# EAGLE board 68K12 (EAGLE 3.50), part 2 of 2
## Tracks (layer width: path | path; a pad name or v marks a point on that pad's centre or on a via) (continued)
D6  (via drill 0.61 pad 1.02) (continued)
  Top 0.254: 123.42,15.7 123.42,29.16 122.4,30.18 122.4,31.57 123.42,32.59 123.42,33.48 v123.42,46.43 122.4,47.45 122.4,49.23 123.42,50.24 123.42,51.26 123.42,52.65 122.66,53.42 122.66,65.61 122.4,65.86 122.4,67.26 122.91,67.77 122.91,68.53 123.42,69.04 | v51.28,90.5 51.28,90.88 33.25,90.88 33.25,69.29 36.55,65.99 36.55,60.27 34.77,58.5 34.77,10.62 v35.79,10.62 | v81.51,55.45 80.49,56.46 80.49,65.48 80.75,65.74 80.75,69.55 78.71,71.58 77.95,71.58 76.94,72.59 v76.94,76.4 75.29,78.05 v75.29,78.82 | v54.84,90.5 59.92,85.42 59.92,80.47
  Bottom 0.254: 53.57,9.35 51.03,9.35 49.76,8.08 42.14,8.08 42.14,9.86 41.38,10.62 v35.79,10.62 | v76.94,76.4 79.48,76.4 80.49,75.39 82.78,75.39 | 59.92,80.47 59.92,78.18 74.65,78.18 v75.29,78.82 | v51.28,90.5 v54.84,90.5 | v123.42,46.43 103.86,46.43 103.1,47.19 103.1,48.08 102.46,48.72 101.32,48.72 100.69,48.08 100.69,46.81 100.05,46.18 96.24,46.18 95.48,46.94 95.48,49.23 93.07,49.23 91.8,50.5 85.95,50.5 81.51,54.94 v81.51,55.45
D7  (via drill 0.61 pad 1.02)
  Top 0.254: 125.96,15.7 v125.96,20.52 125.96,28.4 124.94,29.41 124.94,31.57 125.96,32.59 125.96,33.48 125.96,47.19 124.94,48.21 124.94,49.48 125.96,50.5 125.96,51.26 125.96,64.72 124.94,65.74 124.94,67.01 125.45,67.51 125.45,68.53 125.96,69.04 | v62.46,89.23 62.46,80.47 | v131.29,70.56 131.04,70.82 131.04,82.25 130.02,83.26 130.02,86.06 129.77,86.31 v129.77,89.1 | v57.63,11.89 57.63,9.09 56.62,8.08 55.09,8.08 53.82,6.81 53.57,6.81
  Bottom 0.254: 62.46,80.47 63.86,79.07 73.51,79.07 74.52,80.09 76.05,80.09 77.06,79.07 84.18,79.07 85.32,77.93 | v131.29,70.56 127.48,70.56 125.96,69.04 | v57.63,11.89 61.32,11.89 62.59,13.16 65.25,13.16 65.25,15.19 68.3,18.24 69.19,18.24 69.95,17.48 71.6,17.48 72.11,17.98 88.75,17.98 92.68,21.92 104.88,21.92 106.27,20.52 v125.96,20.52 | 51.03,6.81 53.57,6.81 | v62.46,89.23 71.48,89.23 72.11,88.6 103.1,88.6 104.11,89.61 115.8,89.61 116.81,90.63 122.66,90.63 123.93,89.36 129.51,89.36 v129.77,89.1
DX0
  Bottom 0.305: 43.41,27.13 40.87,29.67 40.87,29.92 39.47,31.32 39.47,33.6 38.33,34.75 34.52,34.75 33.25,33.48 21.82,33.48 20.55,34.75 17.37,34.75 16.1,36.02 15.47,36.02 14.83,36.02 13.56,37.29 6.58,37.29 5.31,38.56
DX1
  Bottom 0.305: 5.31,36.02 6.58,34.75 13.56,34.75 14.83,33.48 15.47,33.48 16.1,33.48 17.37,32.21 20.55,32.21 21.82,30.94 33.88,30.94 35.15,32.21 38.33,32.21 38.33,31.57 39.6,30.3 39.6,29.03 40.87,27.76 40.87,27.13 43.41,24.59
DX2
  Bottom 0.305: 5.31,33.48 6.58,32.21 13.56,32.21 14.83,30.94 15.47,30.94 16.1,30.94 17.37,29.67 20.55,29.67 21.82,28.4 33.88,28.4 35.15,29.67 38.33,29.67 38.33,29.03 39.6,27.76 39.6,26.49 40.87,25.22 40.87,24.59 43.41,22.05
DX3
  Bottom 0.305: 5.31,30.94 6.58,29.67 13.56,29.67 14.83,28.4 15.47,28.4 16.1,28.4 17.37,27.13 20.55,27.13 21.82,25.86 33.88,25.86 35.15,27.13 38.33,27.13 38.33,26.49 39.6,25.22 39.6,23.95 40.87,22.68 40.87,22.05 43.41,19.51
DX4
  Bottom 0.305: 5.31,28.4 6.58,27.13 13.56,27.13 14.83,25.86 15.47,25.86 16.1,25.86 17.37,24.59 20.55,24.59 21.82,23.32 33.88,23.32 35.15,24.59 38.33,24.59 38.33,23.95 39.6,22.68 39.6,21.41 40.87,20.14 40.87,19.51 43.41,16.97
DX5
  Bottom 0.305: 5.31,25.86 6.58,24.59 13.56,24.59 14.83,23.32 15.47,23.32 16.1,23.32 17.37,22.05 20.55,22.05 21.82,20.78 33.88,20.78 35.15,22.05 38.33,22.05 38.33,21.41 39.6,20.14 39.6,18.87 40.87,17.6 40.87,16.97 43.41,14.43
DX6
  Bottom 0.305: 5.31,23.32 6.58,22.05 13.56,22.05 14.83,20.78 15.47,20.78 16.1,20.78 17.37,19.51 20.55,19.51 21.82,18.24 34.52,18.24 35.79,19.51 38.33,19.51 38.33,18.87 39.6,17.6 39.6,16.33 40.87,15.06 40.87,14.43 43.41,11.89
DX7
  Bottom 0.305: 5.31,20.78 6.58,19.51 12.93,19.51 14.2,18.24 15.47,18.24 16.1,18.24 17.37,16.97 20.55,16.97 21.82,15.7 35.15,15.7 36.42,16.97 38.33,16.97 38.33,16.33 39.6,15.06 39.6,13.16 40.87,11.89 41.88,11.89 43.41,10.36 43.41,9.35
FC0  (via drill 0.61 pad 1.02)
  Top 0.254: 101.83,55.07 v101.83,65.23
  Bottom 0.254: v101.83,65.23 105.64,65.23
FC1  (via drill 0.61 pad 1.02)
  Top 0.254: v108.18,58.37 108.18,60.27 107.16,61.29 107.16,64.21 108.18,65.23
  Bottom 0.254: v108.18,58.37 108.18,58.12 105.89,58.12 104.37,56.59 100.81,56.59 99.29,55.07
FC2  (via drill 0.61 pad 1.02)
  Top 0.254: v105.13,58.62 104.62,59.13 104.62,61.67 105.64,62.69
  Bottom 0.254: v105.13,58.62 103.61,58.62 102.08,57.1 98.02,57.1 96.75,55.83 96.75,55.07
GND  (via drill 0.61 pad 1.02)
  Top 0.305: 136.12,11.89 136.12,9.35 | 123.42,4.27 123.42,6.81 v118.34,6.81 | 66.27,25.86 65,27.13 63.73,27.13 | 63.73,27.13 63.73,24.59 | 63.73,29.67 63.73,27.13
  Top 0.508: 113.89,84.28 115.8,84.28 | 113.89,66.5 115.8,66.5 | 113.89,48.72 115.8,48.72 | 113.89,30.94 115.8,30.94
  Top 0.61: 8.61,70.31 11.91,70.31 | 84.68,28.4 84.68,30.81 86.59,32.72 86.59,33.48
  Top 0.813: 156.44,84.28 158.98,81.74 158.98,63.96 | 158.98,63.96 156.57,63.96 | 158.98,46.18 158.98,63.96 | 158.98,46.18 156.69,46.18 | 158.98,28.4 158.98,46.18 | 158.98,28.4 156.69,28.4 | 158.98,28.4 158.98,14.05 156.44,14.05 | v113.89,93.17 113.89,84.28 113.89,66.5 113.89,48.72 113.89,30.94 113.89,14.43 v114.53,13.79
  Top 1.016: 18.01,69.04 16.48,70.56 14.2,70.56 13.94,70.31 11.91,70.31 | 8.61,70.31 7.85,71.07 7.85,88.85 7.34,89.36 5.31,89.36 | v90.4,94.56 90.4,85.55 90.4,83.01 90.4,77.93 92.94,75.39 92.94,62.69 92.94,60.15 | v118.34,6.81 123.42,11.89 | v55.47,62.69 55.47,60.15 52.93,57.61 52.93,51.89 55.47,49.35 | v92.3,4.9 v92.3,15.7 v92.3,33.48 92.3,36.02 | 76.43,52.53 79.73,52.53 | 76.43,52.53 v76.43,56.97 | 76.43,52.53 v76.43,46.81 76.43,34.75 | 76.43,34.75 73.89,34.75 | 76.43,34.75 v76.43,35.51 | 76.43,29.67 76.43,34.75 | v73.25,29.67 73.25,5.92 72.87,5.92 | 72.87,5.92 74.4,4.39 | 72.87,5.92 71.22,5.92 69.57,4.27 63.73,4.27 61.82,6.17 60.55,6.17 | v61.19,29.67 61.19,11.89 60.55,11.25 60.55,6.17 | 60.55,6.17 58.01,6.17 56.11,4.27 51.03,4.27 v48.49,6.81 | 23.09,52.53 29.44,52.53 31.34,50.62 v31.34,9.35
  Bottom 0.254: 26.62,60.4 26.64,60.4 24.99,62.05 24.99,65.86
  Bottom 0.305: 26.9,77.93 28.17,79.2 35.79,79.2 37.06,80.47 37.06,86.18 42.14,86.18 | v118.34,6.81 115.8,6.81 | 76.43,29.67 76.43,27.13 | 40.87,68.4 41.5,68.4 40.87,67.77 40.87,65.86 40.87,68.4
  Bottom 0.508: v118.34,6.81 118.34,5.54 110.72,5.54 110.08,6.17 107.54,6.17 106.27,4.9 | v92.3,33.48 96.75,33.48
  Bottom 0.61: 45.95,32.21 47.22,30.94 51.03,30.94 | 51.03,30.94 51.03,29.67 | 54.84,30.94 51.03,30.94 | 37.06,8.08 39.6,8.08
  Bottom 0.813: 152.63,88.09 156.44,84.28
  Bottom 1.016: 24.99,65.86 23.72,65.86 20.55,69.04 18.01,69.04 | 148.18,88.09 143.74,88.09 | 148.18,88.09 152.63,88.09 | 148.18,88.09 148.18,90.63 145.64,93.17 130.28,93.17 129.77,92.66 124.18,92.66 123.67,93.17 v113.89,93.17 111.99,93.17 111.48,92.66 105.64,92.66 105.64,93.8 | 5.31,89.36 7.85,91.9 7.85,93.17 7.85,95.07 10.13,97.36 44.68,97.36 | 44.68,97.36 74.27,97.36 79.48,92.15 85.7,92.15 88.11,94.56 v90.4,94.56 91.54,94.56 94.21,91.9 99.29,91.9 99.92,91.9 101.83,93.8 105.64,93.8 | 105.64,93.8 105.64,95.07 | 44.68,97.36 44.68,95.71 44.68,88.72 42.14,86.18 42.14,80.47 44.04,78.56 44.04,68.4 40.87,68.4 40.87,65.86 43.41,63.32 43.41,62.69 48.49,62.69 50.39,64.59 53.57,64.59 v55.47,62.69 | 156.44,14.05 155.55,13.16 152.63,13.16 146.53,13.16 145.26,11.89 143.48,11.89 | 143.48,11.89 143.48,10.74 | 143.48,11.89 136.12,11.89 131.17,11.89 129.26,13.79 127.61,13.79 125.96,12.14 125.96,11.89 123.42,11.89 119.86,11.89 117.96,13.79 v114.53,13.79 | 92.94,60.15 95.48,60.15 92.94,60.15 | 92.94,60.15 89.76,56.97 84.05,56.97 | v92.3,4.9 106.27,4.9 | v92.3,15.7 104.37,15.7 | 84.05,56.97 84.05,55.07 | 73.89,57.61 75.79,57.61 v76.43,56.97 84.05,56.97 | 61.19,49.35 55.47,49.35 | 61.19,49.35 61.19,46.81 | 61.19,49.35 73.89,49.35 73.89,46.81 v76.43,46.81 | 86.59,35.26 87.35,36.02 92.3,36.02 | 86.59,35.26 86.59,33.48 | v76.43,35.51 80.75,35.51 81,35.26 86.59,35.26 | 43.41,39.83 45.95,37.29 45.95,32.21 | v73.25,29.67 76.43,29.67 | 54.84,30.94 56.11,29.67 v61.19,29.67 63.73,29.67 | 45.95,6.81 v48.49,6.81 | 45.95,6.81 45.95,4.27 | 45.95,6.81 43.41,6.81 40.87,6.81 39.6,8.08 | 37.06,8.08 32.61,8.08 v31.34,9.35
I0  (via drill 0.61 pad 1.02)
  Top 0.305: v14.2,86.18 14.2,90.63 19.28,95.71
  Bottom 0.305: v14.2,86.18 13.56,86.18 11.66,84.28 10.39,84.28
I1  (via drill 0.61 pad 1.02)
  Top 0.305: 5.31,84.28 4.04,84.28 4.04,88.09 v6.58,88.09
  Bottom 0.305: v6.58,88.09 6.58,88.72 9.5,91.64 11.02,91.64 13.44,94.06 15.09,94.06 16.74,95.71
I2
  Top 0.305: 14.2,95.71 11.02,95.71 9.12,93.8 9.12,88.09 10.39,86.82
I3  (via drill 0.61 pad 1.02)
  Top 0.305: v9.12,75.39 11.02,75.39 14.2,78.56 14.2,80.47
  Bottom 0.305: 5.31,74.12 6.58,75.39 v9.12,75.39
I4
  Top 0.305: 10.39,74.12 11.02,74.12 16.74,79.83 16.74,80.47
I5  (via drill 0.61 pad 1.02)
  Top 0.305: v12.8,73.99 19.28,80.47
  Bottom 0.305: 15.47,66.5 16.74,67.77 16.74,73.99 v12.8,73.99 11.66,72.85 6.58,72.85 5.31,71.58
I6
  Top 0.305: 10.39,71.58 12.93,71.58 21.82,80.47
I7  (via drill 0.61 pad 1.02)
  Top 0.305: v15.47,72.21 16.1,72.21 24.36,80.47
  Bottom 0.305: 5.31,69.04 6.58,70.31 15.47,70.31 | 15.47,70.31 ST2. | 15.47,70.31 v15.47,72.21
N$1
  Bottom 0.254: 151.36,79.2 152.5,78.05 155.42,78.05 155.42,71.32 154.41,70.31 153.14,70.31 151.87,69.04 151.36,69.04
N$2
  Bottom 0.254: 153.9,69.04 156.44,69.04 157.71,70.31 157.71,76.66 156.44,76.66
N$3  (via drill 0.61 pad 1.02)
  Top 0.254: v142.72,71.58 v142.72,76.66
  Bottom 0.254: v142.72,71.58 143.74,70.56 143.74,69.04 | v142.72,76.66 144.25,76.66 147.93,80.34 152.37,80.34 153.52,79.2 153.9,79.2
N$4  (via drill 0.61 pad 1.02)
  Top 0.254: v94.97,64.21 94.46,63.7 94.46,58.88 95.48,57.86 95.48,49.48 94.21,48.21 94.21,47.45
  Bottom 0.254: v94.97,64.21 103.1,64.21 103.1,63.96 | 103.1,63.96 103.1,62.69 | 103.1,63.96 106.91,63.96 108.18,62.69
N$6  (via drill 0.61 pad 1.02)
  Top 0.254: v105.64,50.5 105.64,56.59 106.15,57.1 106.15,59.64 105.64,60.15
  Bottom 0.254: 96.75,47.45 99.8,50.5 v105.64,50.5
N$7  (via drill 0.61 pad 1.02)
  Top 0.254: v75.67,64.21 v75.67,75.39
  Bottom 0.254: v75.67,64.21 77.7,64.21 77.95,63.96 86.59,63.96 87.86,62.69 | v75.67,75.39 78.33,75.39
N$8  (via drill 0.61 pad 1.02)
  Top 0.254: v81.51,59.13 81.25,59.39 81.25,69.8 78.46,72.59 78.46,72.85 78.33,72.85
  Bottom 0.254: v81.51,59.13 86.84,59.13 87.86,60.15
N$10
  Bottom 0.254: 146.28,69.04 146.28,71.32 146.53,71.58 148.82,71.58
N$11
  Top 0.254: 148.82,76.66 147.8,77.67 147.8,82.5 148.82,83.52 148.82,84.28
N$12
  Bottom 0.254: 153.9,74.12 153.9,73.48 152.63,72.21 152.63,70.82 152.12,70.31 150.72,70.31 149.45,69.04 148.82,69.04
N$13  (via drill 0.61 pad 1.02)
  Top 0.305: 29.44,95.71 29.44,93.29 52.3,93.29 52.3,84.28 51.03,83.01 v51.03,81.74
  Bottom 0.305: v51.03,81.74 51.03,79.83 49.76,78.56 47.22,78.56 46.58,77.93 46.58,71.2 | 46.58,71.2 48.36,71.2 | 46.58,71.2 46.58,69.04 45.95,68.4
N$14  (via drill 0.61 pad 1.02)
  Top 0.254: v54.33,53.29 54.33,57.1 v54.84,57.61 | v66.27,60.15 66.27,65.23
  Bottom 0.254: v54.33,53.29 56.11,53.29 57.12,52.27 61.7,52.27 62.2,51.77 63.22,51.77 63.73,52.27 72.36,52.27 72.36,51.26 80.37,51.26 82.91,48.72 82.91,46.18 87.86,46.18 89.13,44.91 | v54.84,57.61 56.11,57.61 58.14,59.64 65.76,59.64 v66.27,60.15
  Bottom 0.305: 63.73,65.23 66.27,65.23 67.54,63.96 70.71,63.96 71.35,64.59 71.35,65.23
N$15  (via drill 0.61 pad 1.02)
  Top 0.254: v72.62,59.13 72.62,57.23 73.89,55.96 73.89,54.43
  Bottom 0.254: v72.62,59.13 60.17,59.13 58.65,57.61
N$16
  Bottom 0.305: 128.5,6.81 126.72,6.81 125.45,5.54 122.15,5.54 119.61,8.08 113.89,8.08 113.26,8.71 112.62,8.71 111.99,9.35
N$17  (via drill 0.61 pad 1.02)
  Top 0.305: v49.12,89.99 48.49,89.36 35.79,89.36 35.79,79.2 37.69,79.2 38.33,78.56 38.33,77.29 38.96,76.66 42.14,76.66 42.14,77.93
  Bottom 0.305: 52.3,95.71 49.12,92.53 v49.12,89.99
N$18  (via drill 0.61 pad 1.02)
  Top 0.254: v157.2,51 158.22,51 158.22,59.89 157.96,60.15 v157.71,60.15
  Bottom 0.254: v157.71,60.15 152.63,60.15 151.36,61.42 | 151.36,51.26 152.63,49.99 154.91,49.99 155.93,51 v157.2,51
N$19  (via drill 0.61 pad 1.02)
  Top 0.305: 31.98,95.71 31.98,94.31 53.57,94.31 v53.57,78.94
  Bottom 0.305: 50.39,76.28 48.36,76.28 | 50.39,76.28 50.39,69.16 47.09,65.86 45.95,65.86 | 50.39,76.28 50.39,77.29 52.04,78.94 v53.57,78.94
N$20  (via drill 0.61 pad 1.02)
  Top 0.254: v157.2,52.78 157.45,53.04 157.45,57.86 156.44,58.88
  Bottom 0.254: v157.2,52.78 155.42,52.78 153.9,51.26
N$21  (via drill 0.61 pad 1.02)
  Top 0.254: v142.72,53.8 v142.72,62.43
  Bottom 0.254: v142.72,53.8 142.72,52.27 143.74,51.26 | v142.72,62.43 152.5,62.43 153.52,61.42 153.9,61.42
N$22
  Bottom 0.254: 146.28,51.26 146.28,53.8 148.82,53.8
N$23
  Bottom 0.305: 78.97,33.48 78.97,31.83 79.98,30.81 82.14,30.81
N$24
  Bottom 0.254: 84.05,33.48 85.06,32.46 87.86,32.46 89.89,34.49 93.95,34.49 93.95,36.02 93.93,36.02
N$25
  Top 0.254: 148.82,58.88 147.8,59.89 147.8,62.69 148.82,63.7 148.82,66.5
N$26
  Bottom 0.254: 148.82,51.26 149.58,51.26 150.85,52.53 152.12,52.53 152.63,53.04 152.63,54.56 153.9,55.83 153.9,56.34
N$27
  Bottom 0.305: 26.9,70.31 26.9,65.86 26.62,65.86
N$28
  Bottom 0.254: 24.99,60.4 24.99,59.26 35.41,59.26 37.69,61.54 37.69,69.67 37.06,70.31
N$30
  Top 0.305: 66.27,18.24 66.27,20.78
  Bottom 0.305: 63.73,16.97 65,18.24 66.27,18.24
N$32
  Bottom 0.254: 31.98,70.31 32.23,70.31 35.66,66.88 35.66,63.58 33.12,61.04 33.12,60.4 33.15,60.4
N$33
  Bottom 0.305: 34.52,70.31 36.42,68.4 36.42,62.05 34.77,60.4
N$34  (via drill 0.61 pad 1.02)
  Top 0.305: v50.39,89.36 49.12,88.09 38.33,88.09 38.33,79.83 39.6,78.56 39.6,77.93
  Bottom 0.305: v50.39,89.36 50.39,92.79 51.54,93.93 53.06,93.93 54.84,95.71
N$55  (via drill 0.61 pad 1.02)
  Top 0.254: v124.43,75.64 124.43,89.1 123.42,90.12 123.42,95.71 | 128.5,69.04 v128.5,75.64
  Bottom 0.254: v128.5,75.64 v124.43,75.64
N$57  (via drill 0.61 pad 1.02)
  Top 0.254: v115.54,63.45 114.78,62.69 114.78,54.43 115.67,53.54 v115.8,53.54 | v124.43,63.45 124.43,67.51 124.94,68.02 124.94,70.05 125.45,70.56 125.45,83.01 124.94,83.52 124.94,85.29 126.97,87.33 126.97,94.69 125.96,95.71
  Bottom 0.254: v115.54,63.45 v124.43,63.45 | 128.5,51.26 126.85,52.91 121.39,52.91 120.75,53.54 v115.8,53.54
N$58  (via drill 0.61 pad 1.02)
  Top 0.254: v157.2,33.6 158.09,34.49 158.09,41.73 157.71,42.11 v157.71,44.78
  Bottom 0.254: 151.36,33.48 152.63,32.21 155.8,32.21 v157.2,33.6 | 151.36,43.64 151.99,43.64 153.14,44.78 v157.71,44.78
N$59  (via drill 0.61 pad 1.02)
  Top 0.254: v157.07,36.02 157.45,36.4 157.45,40.08 156.44,41.1
  Bottom 0.254: v157.07,36.02 154.53,33.48 153.9,33.48
N$60  (via drill 0.61 pad 1.02)
  Top 0.254: v119.35,28.65 119.35,32.21 119.86,32.72 119.86,39.07 118.85,40.08 v118.85,44.65
  Bottom 0.254: 143.74,33.48 144.75,32.46 144.75,28.78 143.1,27.13 133.32,27.13 131.04,29.41 120.12,29.41 v119.35,28.65 | v118.85,44.65 150.09,44.65 150.09,42.88 150.34,42.62 152.37,42.62 153.39,43.64 153.9,43.64
N$61
  Bottom 0.254: 146.28,33.48 146.79,33.99 146.79,36.02 148.82,36.02
N$62
  Top 0.254: 148.82,41.1 147.8,42.11 147.8,44.65 148.31,45.16 148.31,48.21 148.82,48.72
N$63
  Bottom 0.254: 148.82,33.48 149.33,33.48 150.6,34.75 152.12,34.75 152.63,35.26 152.63,37.29 153.9,38.56
N$91  (via drill 0.61 pad 1.02)
  Top 0.254: v134.59,35 134.59,67.77 135.1,68.28 135.1,75.77 134.85,76.02 134.85,94.44 132.31,94.44 131.04,95.71
  Bottom 0.254: v134.59,35 130.02,35 128.5,33.48
N$92  (via drill 0.61 pad 1.02)
  Top 0.254: v146.91,94.44 149.33,94.44 155.55,88.21 157.71,88.21 157.71,85.67 156.06,85.67 155.04,84.66 155.04,83.01 153.64,83.01 152.88,82.25 152.88,77.29 152.63,77.04 152.63,63.58 152.37,63.32 152.37,28.91 152.63,28.65 152.63,14.94 151.87,14.17 v144.75,14.17
  Bottom 0.254: 128.5,15.7 129.26,15.7 130.78,14.17 v144.75,14.17 | 133.58,95.71 133.58,94.44 v146.91,94.44
N$94
  Top 0.254: 151.36,15.7 150.09,16.97 150.09,21.16 150.34,21.41 150.34,24.84 151.36,25.86
N$95
  Bottom 0.254: 153.9,15.7 154.41,15.7 157.96,19.25 157.96,23.32 156.44,23.32
N$96  (via drill 0.61 pad 1.02)
  Top 0.254: 143.74,15.7 v143.74,24.59
  Bottom 0.254: 153.9,25.86 153.14,25.86 151.87,24.59 v143.74,24.59
N$97
  Top 0.254: 146.28,15.7 148.82,18.24
N$98
  Top 0.254: 148.82,23.32 147.29,24.84 147.29,27.38 148.82,28.91 148.82,30.94
N$99
  Bottom 0.254: 148.82,15.7 149.83,16.71 154.41,16.71 155.17,17.48 155.17,19.13 153.9,20.4 153.9,20.78
PA0
  Bottom 0.305: 10.39,53.8 13.56,53.8 14.83,52.53 16.1,52.53 17.37,51.26 18.01,51.26 20.55,51.26 21.82,49.99 23.09,49.99
PA1
  Bottom 0.305: 10.39,51.26 13.56,51.26 14.83,49.99 16.1,49.99 17.37,48.72 18.01,48.72 20.55,48.72 21.82,47.45 23.09,47.45
PA2
  Bottom 0.305: 10.39,48.72 13.56,48.72 14.83,47.45 16.1,47.45 17.37,46.18 18.01,46.18 20.55,46.18 21.82,44.91 23.09,44.91
PA3
  Bottom 0.305: 10.39,46.18 13.56,46.18 14.83,44.91 16.1,44.91 17.37,43.64 18.01,43.64 20.55,43.64 21.82,42.37 23.09,42.37
PA4
  Bottom 0.305: 10.39,43.64 13.56,43.64 14.83,42.37 16.1,42.37 17.37,41.1 18.01,41.1 20.55,41.1 21.82,39.83 23.09,39.83
PA5
  Bottom 0.305: 10.39,41.1 13.56,41.1 14.83,39.83 16.1,39.83 17.37,38.56 18.01,38.56 20.55,38.56 21.82,37.29 23.09,37.29
PA6
  Bottom 0.305: 10.39,38.56 13.56,38.56 14.83,37.29 16.1,37.29 17.37,36.02 18.01,36.02 20.55,36.02 21.82,34.75 23.09,34.75
PA7
  Bottom 0.305: 10.39,36.02 13.56,36.02 14.83,34.75 16.1,34.75 17.37,33.48 18.01,33.48 20.55,33.48 21.82,32.21 23.09,32.21
PB0
  Bottom 0.305: 10.39,33.48 13.56,33.48 14.83,32.21 16.1,32.21 17.37,30.94 18.01,30.94 20.55,30.94 21.82,29.67 23.09,29.67
PB1
  Bottom 0.305: 10.39,30.94 13.56,30.94 14.83,29.67 16.1,29.67 17.37,28.4 18.01,28.4 20.55,28.4 21.82,27.13 23.09,27.13
PB2
  Bottom 0.305: 10.39,28.4 13.56,28.4 14.83,27.13 16.1,27.13 17.37,25.86 18.01,25.86 20.55,25.86 21.82,24.59 23.09,24.59
PB3
  Bottom 0.305: 10.39,25.86 13.56,25.86 14.83,24.59 16.1,24.59 17.37,23.32 18.01,23.32 20.55,23.32 21.82,22.05 23.09,22.05
PB4
  Bottom 0.305: 10.39,23.32 13.56,23.32 14.83,22.05 16.1,22.05 17.37,20.78 18.01,20.78 20.55,20.78 21.82,19.51 23.09,19.51
PB5
  Bottom 0.305: 10.39,20.78 12.93,20.78 14.2,19.51 16.1,19.51 17.37,18.24 18.01,18.24 20.55,18.24 21.82,16.97 23.09,16.97
PB6
  Bottom 0.305: 10.39,18.24 12.93,18.24 14.2,16.97 16.1,16.97 17.37,15.7 18.01,15.7 20.55,15.7 21.82,14.43 23.09,14.43
PB7
  Bottom 0.305: 10.39,15.7 12.93,15.7 14.2,14.43 16.1,14.43 17.37,13.16 18.01,13.16 20.55,13.16 21.82,11.89 23.09,11.89
PHI2  (via drill 0.61 pad 1.02)
  Top 0.305: 38.33,14.43 38.96,14.43 40.23,15.7 v44.68,15.7 | 53.57,38.56 57.38,38.56 59.92,36.02 59.92,16.33 v59.28,15.7 v59.28,9.73 | 66.27,8.08 62.46,8.08 62.46,9.35 v62.08,9.73
  Bottom 0.305: 5.31,18.24 6.58,16.97 12.93,16.97 14.2,15.7 15.47,15.7 16.1,15.7 17.37,14.43 20.55,14.43 21.82,13.16 35.15,13.16 36.42,14.43 38.33,14.43 | 63.73,14.43 62.46,14.43 61.19,15.7 v59.28,15.7 v44.68,15.7 | v59.28,9.73 v62.08,9.73
Q3  (via drill 0.61 pad 1.02)
  Top 0.305: 43.41,32.21 43.41,34.75 | v47.85,13.16 47.85,14.43 49.76,16.33 v49.76,25.86
  Bottom 0.305: v47.85,13.16 54.2,13.16 55.47,11.89 56.11,11.89 | v49.76,25.86 43.41,32.21
R/W  (via drill 0.61 pad 1.02)
  Top 0.254: v89.38,11.38 89.38,14.94 87.35,16.97 87.35,32.21 87.6,32.46 87.6,34.75 85.06,37.29 85.06,54.31 85.83,55.07 86.08,55.07 | 86.08,55.07 84.05,57.1 84.05,61.42 82.78,62.69 84.05,63.96 84.05,65.99 84.56,66.5 86.08,66.5 88.11,68.53 88.11,74.12 87.1,75.13 87.1,80.09 89.13,82.12 89.13,92.66 v88.87,92.91 | v96.49,52.78 96.49,48.97 95.48,47.96 95.48,45.92 96.49,44.91 96.75,44.91 | 86.08,55.07 86.59,55.07
  Top 0.305: v70.59,11.89 69.32,10.62 68.17,10.62 66.9,9.35 63.73,9.35 | v47.22,26.49 46.84,26.49 v46.84,10.62
  Bottom 0.254: v88.87,92.91 87.86,92.91 86.08,91.14 77.19,91.14 72.62,95.71 | v89.38,11.38 89.38,11.89 79.73,11.89 78.71,10.87 77.44,10.87 76.43,11.89 | 86.59,55.07 86.59,52.78 v96.49,52.78
  Bottom 0.305: 43.41,29.67 44.04,29.67 v47.22,26.49 | v46.84,10.62 62.46,10.62 63.73,9.35 | v70.59,11.89 76.43,11.89
RW_BUF
  Top 0.305: 38.33,6.81 39.6,8.08 45.95,8.08 49.12,11.25 49.12,14.43 50.39,15.7 54.84,15.7 54.84,18.24 57.38,18.24 57.38,27.13 56.11,27.13
  Bottom 0.305: 38.33,6.81 30.71,6.81 26.9,10.62 21.82,10.62 20.55,11.89 17.37,11.89 16.1,13.16 15.47,13.16 14.2,13.16 12.93,14.43 6.58,14.43 5.31,15.7
RXC/TXC
  Top 0.305: 49.76,96.98 57.38,96.98 57.38,95.71 | 27.53,92.53 28.17,93.17 28.17,96.98 49.76,96.98 | 49.76,96.98 49.76,95.71
  Bottom 0.305: 5.31,81.74 5.69,81.74 9.5,85.55 11.66,85.55 14.2,88.09 21.18,88.09 25.63,92.53 27.53,92.53
RXD  (via drill 0.61 pad 1.02)
  Top 0.305: v34.52,74.12 36.3,72.34 40.74,72.34 42.14,70.94 42.14,70.31
  Bottom 0.305: 5.31,76.66 6.58,77.93 11.02,77.93 12.29,76.66 23.72,76.66 26.26,74.12 v34.52,74.12
S$1
  Top 0.254: 0,5.08 0,0 5.08,0
S$2
  Top 0.254: 0,94.92 0,100 5.08,100
S$3
  Top 0.254: 159.99,94.92 159.99,100 154.91,100
S$4
  Top 0.254: 154.91,0 159.99,0 159.99,5.08
S$5
  Bottom 0.254: 0,5.08 0,0 5.08,0
S$6
  Bottom 0.254: 0,94.92 0,100 5.08,100
S$7
  Bottom 0.254: 159.99,94.92 159.99,100 154.91,100
S$8
  Bottom 0.254: 154.91,0 159.99,0 159.99,5.08
S$9
  Top 0.305: 138.53,3.89 137.39,3.89 137.39,5.16 136.12,6.43 136.12,6.81
S$10
  Bottom 0.305: 136.12,4.27 137.9,6.05 140.44,6.05 | 140.44,6.05 140.44,3.89 | 140.44,6.05 143.23,6.05 143.48,5.79 143.48,5.66
S$11
  Bottom 0.254: 29.44,70.31 31.09,68.66 32.74,68.66 34.65,66.75 34.65,65.86
S$12  (via drill 0.61 pad 1.02)
  Top 0.254: v32.99,65.86 33.02,65.86
  Bottom 0.254: 24.36,70.31 25.88,71.83 28.17,71.83 28.17,69.29 31.6,65.86 v32.99,65.86
S$14
  Route3 0.254: 71.35,71.2 71.35,69.42
S$15
  Route3 0.254: 27.53,90.37 27.53,92.15
S$16
  Route3 0.254: 53.57,40.72 53.57,38.94
S$17
  Route2 0.254: 153.9,81.23 153.9,79.71
S$18
  Route2 0.254: 148.82,73.61 148.82,72.09
S$19
  Route2 0.254: 149.33,76.66 150.85,76.66
S$20
  Route2 0.254: 151.87,74.12 153.39,74.12
S$21
  Route2 0.254: 153.9,63.45 153.9,61.93
S$22
  Route2 0.254: 149.33,58.88 150.85,58.88
S$23
  Route2 0.254: 151.87,56.34 153.39,56.34
S$24
  Route2 0.254: 148.82,55.83 148.82,54.31
S$25
  Route2 0.254: 154.41,38.56 155.93,38.56
S$26
  Route2 0.254: 149.33,36.02 150.72,36.02
S$27
  Route2 0.254: 153.9,43.13 153.9,41.48
S$28
  Route2 0.254: 154.41,20.78 155.93,20.78
S$29
  Route2 0.254: 149.33,18.24 150.85,18.24
S$30
  Route2 0.254: 153.9,25.35 153.9,23.83
S$31
  Route2 0.254: 39.6,70.82 39.6,77.42
S$32
  Route2 0.254: 42.14,70.69 42.14,77.42
SCL  (via drill 0.61 pad 1.02)
  Top 0.305: v107.54,26.49 v107.54,12.01
  Bottom 0.305: 128.5,9.35 127.23,8.08 121.51,8.08 120.24,9.35 115.8,9.35 114.02,9.35 111.99,11.38 111.99,11.89 107.54,11.89 107.42,12.01 v107.54,12.01 | 68.81,22.05 74.52,22.05 75.79,20.78 77.7,20.78 78.97,19.51 82.14,19.51 83.41,20.78 82.14,22.05 82.14,24.59 82.78,25.22 92.81,25.22 94.72,27.13 107.54,27.13 v107.54,26.49
SCL_EXT
  Top 0.305: 18.01,63.96 19.91,63.96 19.91,32.21 21.18,30.94 29.44,30.94 29.44,3 74.65,3 75.67,4.01 75.67,5.28 75.92,5.54 77.44,5.54 80.24,8.33 80.24,16.97 82.78,19.51 84.43,19.51 84.43,22.3 83.41,23.32
  Bottom 0.305: 10.39,66.5 13.56,66.5 14.83,65.23 16.1,65.23 17.37,63.96 18.01,63.96
SDA  (via drill 0.61 pad 1.02)
  Top 0.254: v108.81,27.76 108.81,22.17 111.99,19 111.99,15.7
  Top 0.305: 111.99,15.7 111.99,14.43
  Bottom 0.305: 68.81,24.59 74.52,24.59 75.79,23.32 77.06,23.32 79.6,20.78 81.51,22.68 81.51,25.22 82.52,26.24 91.54,26.24 93.07,27.76 v108.81,27.76 | 111.99,14.43 114.53,11.89 115.8,11.89 116.43,11.89 117.7,10.62 126.72,10.62 127.99,11.89 128.5,11.89
SDA_EXT  (via drill 0.61 pad 1.02)
  Top 0.305: 18.01,61.42 19.28,61.42 19.28,29.67 20.55,28.4 28.17,28.4 28.17,2.36 75.03,2.36 v76.94,4.27 | 79.6,23.32 78.33,22.05 78.33,18.87 78.97,18.24 78.97,9.09 77.95,8.08 74.78,8.08 v74.78,6.43
  Bottom 0.305: 10.39,63.96 13.56,63.96 14.83,62.69 16.1,62.69 17.37,61.42 18.01,61.42 | v76.94,4.27 v74.78,6.43
TAI
  Bottom 0.305: 26.9,95.71 22.45,91.26 13.56,91.26 11.66,89.36 ST3.
TAO
  Bottom 0.305: 10.39,79.2 11.02,79.2 14.2,82.37 28.8,82.37 42.14,95.71
TBI
  Bottom 0.305: 24.36,95.71 21.18,92.53 13.56,92.53 11.66,90.63 9.63,90.63 8.99,89.99 8.99,88.72 7.09,86.82 5.31,86.82
TBO
  Bottom 0.305: 5.31,79.2 6.58,80.47 11.02,80.47 14.2,83.64 27.53,83.64 39.6,95.71
TCO
  Bottom 0.305: 10.39,81.74 13.56,84.91 26.26,84.91 37.06,95.71
TDO
  Top 0.305: 27.53,89.99 JMP5. 25.63,85.55 25.63,74.12 18.01,66.5
  Bottom 0.305: 27.53,89.99 28.8,89.99 34.52,95.71
TXD
  Bottom 0.305: 10.39,76.66 11.02,76.66 12.29,75.39 23.09,75.39 25.63,72.85 37.95,72.85 39.6,71.2 39.6,70.31
VBATT
  Top 0.254: 155.42,38.56 155.42,21.79 156.44,20.78 | 155.42,38.56 156.44,38.56 | 155.42,38.56 155.42,56.34 | 155.42,56.34 156.44,56.34 | 155.42,56.34 155.42,73.1 156.44,74.12
  Top 0.305: 156.44,11.51 154.79,13.16 154.79,14.55 156.44,16.21 156.44,20.78
  Top 0.508: 108.81,4.9 108.81,5.54 | 128.5,4.27 128.5,3 114.53,3 113.89,3.63 113.89,5.54 108.81,5.54 | 108.81,5.54 108.81,10.49 110.08,11.76 110.08,17.6
  Bottom 0.61: 128.5,4.27 130.78,4.27 134.59,8.08 143.99,8.08 147.29,11.38 152.37,11.38 152.63,11.63 152.63,11.53 152.63,11.51 156.44,11.51
VCC  (via drill 0.61 pad 1.02)
  Top 0.254: 151.36,23.32 151.36,20.78 | 151.36,41.1 151.36,38.56 | 151.36,58.88 151.36,56.34 | 151.36,74.12 151.36,76.66 152.37,77.67 152.37,82.75 153.9,84.28 | v89,79.32 89,76.28 v89.89,75.39
  Top 0.305: 38.33,11.89 38.33,11.25 37.06,9.98 37.06,5.54 38.96,5.54 40.23,4.27 40.87,4.27 | 153.9,84.28 153.9,85.67 155.04,86.82 156.44,86.82 | 53.57,27.13 53.57,29.67 51.03,32.21
  Top 0.508: 90.4,60.15 89.13,61.42 89.13,63.32 89.89,64.08 v89.89,75.39 | v96.75,75.39 96.75,84.28 95.48,85.55 | v110.72,50.62 v110.72,90.63 | 82.14,28.4 80.24,30.3 80.24,39.19 78.97,40.46 U3.
  Top 1.016: 99.29,94.44 95.48,90.63 v95.48,89.87 95.48,85.55 | U1. 106.91,44.91 106.91,41.1 | v100.56,41.1 v100.56,39.19 v100.56,23.95 v100.56,3 | IC1. 51.03,65.23 55.47,65.23 U5. 58.65,60.78 56.74,58.88 56.74,55.07 57.38,54.43 | v40.23,84.28 v44.04,84.28 | 10.39,93.17 12.29,91.26 v12.29,78.56 | 37.06,77.93 37.06,74.12 44.04,74.12 44.04,69.8 43.41,69.16 v43.41,65.86 40.87,63.32 40.87,62.69 | 57.38,54.43 U4. | 57.38,51.89 57.38,48.72 56.74,48.08 v56.74,46.05 | 57.38,51.89 55.47,51.89 | 57.38,51.89 57.38,54.43 | 79.73,49.99 79.73,41.86 U3. | v61.19,40.46 v61.19,42.37 v61.19,32.84 v61.19,40.46
  Bottom 0.254: 151.36,23.32 151.87,23.32 153.14,22.05 155.17,22.05 155.17,24.71 156.31,25.86 156.44,25.86 157.96,25.86 157.96,30.94 156.69,30.94 | 158.98,33.22 158.72,33.22 | 151.36,41.1 152.37,40.08 158.98,40.08 | 158.98,43.64 156.44,43.64 | 151.36,58.88 152.37,57.86 158.98,57.86 | 158.98,61.42 156.44,61.42 | 158.98,79.2 156.44,79.2 | v89,79.32 86.84,81.48 81.76,81.48 80.75,80.47 78.33,80.47
  Bottom 0.305: 48.49,37.29 44.68,41.1 42.77,41.1 42.14,40.46 42.14,35.64 40.87,34.37 40.87,32.21 | 123.42,9.35 125.96,9.35 126.59,9.35 127.86,10.62 130.15,10.62 130.15,6.68 129.01,5.54 127.23,5.54 124.69,3 117.07,3 115.8,4.27
  Bottom 0.508: v96.75,75.39 v89.89,75.39 | v40.23,84.28 38.33,84.28 38.33,79.2 37.06,77.93
  Bottom 0.61: 156.69,30.94 153.9,30.94 | 156.69,48.72 153.9,48.72 | 156.57,66.5 153.9,66.5
  Bottom 0.813: 156.69,30.94 158.98,33.22 158.98,40.08 158.98,43.64 158.98,48.72 | 158.98,48.72 156.69,48.72 | 158.98,48.72 158.98,57.86 158.98,61.42 158.98,66.5 | 158.98,66.5 156.57,66.5 | 158.98,66.5 158.98,79.2 158.98,84.28 156.44,86.82
  Bottom 1.016: 58.65,4.27 56.11,6.81 53.57,4.27 48.49,4.27 48.49,2.62 | 110.08,25.22 108.81,23.95 v100.56,23.95 | 115.8,97.36 115.8,95.71 | 115.8,97.36 146.66,97.36 148.18,95.83 148.18,93.17 150.09,93.17 156.44,86.82 | 108.18,97.36 108.18,95.07 | 108.18,97.36 115.8,97.36 | 108.18,97.36 102.21,97.36 99.29,94.44 | v95.48,89.87 102.59,89.87 103.35,90.63 v110.72,90.63 | U1. 109.32,47.45 110.72,48.84 v110.72,50.62 | v100.56,41.1 102.46,41.1 102.97,40.59 106.4,40.59 106.91,41.1 | 47.22,95.71 47.22,87.45 v44.04,84.28 | v12.29,78.56 23.72,78.56 24.36,77.93 26.26,76.02 35.15,76.02 37.06,77.93 | v43.41,65.86 45.31,63.96 47.22,63.96 49.76,66.5 55.47,66.5 55.47,65.23 | v56.74,46.05 56.74,44.27 58.65,42.37 | 58.65,42.37 v61.19,42.37 58.65,42.37 | 48.49,37.29 U11. 51.03,34.11 | 51.03,34.11 56.11,34.11 57.38,32.84 v61.19,32.84 | v61.19,40.46 78.33,40.46 U3. | 81.51,41.1 U3. | 81.51,41.1 U3. | 81.51,41.1 81.51,39.19 v100.56,39.19 | 115.8,4.27 111.99,4.27 110.72,3 v100.56,3 90.53,3 85.45,8.08 81,8.08 78.46,5.54 78.46,3.25 77.83,2.62 71.86,2.62 | 71.86,2.62 71.86,4.39 71.22,4.39 68.81,6.81 | 48.49,2.62 71.86,2.62 | 40.87,2.62 48.49,2.62 | 40.87,2.62 40.87,4.27 | 40.87,2.62 24.74,2.62 23.09,4.27 18.01,4.27 15.47,6.81 15.47,8.08 7.21,8.08 5.31,9.98 5.31,10.62 | 51.03,34.11 51.03,32.21
(copper drawn outside any net)
  shapes: Top area x2

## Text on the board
Top: TxC | ROM | mino | 9/96 | 16 | 8 | 2 | SDA | SCL | BS | RAM | 68k1.2
Bottom: 0V | TBin | I1 | TDO | TCO | TBO | TAO | RxD | TxD | i3 | i4 | i5 | i6 | i7 | /r | /cs0 | scl | /cs1 | sda | a7 | it7 | a6 | ca1 | a5 | ca2 | a4 | Pa0 | a0 | Pa1 | a1 | Pa2 | a2 | Pa3 | a3 | Pa4 | /res | Pa5 | d0 | Pa6 | d1 | Pa7 | d2 | Pb0 | d3 | Pb1 | d4 | Pb2 | d5 | Pb3 | d6 | Pb4 | d7 | Pb5 | Phi2 | Pb6 | r/w | Pb7 | int2 | cb1 | +5 | cb2 | LS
